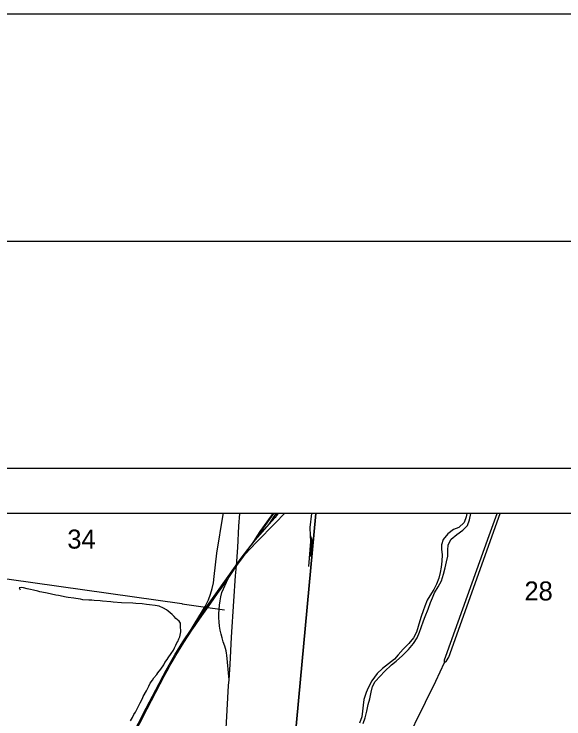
# Model space of a CAD drawing. Extents: x 0 to 34, y -3.9 to 26.2.
# Drawn here: x 3.566 to 4.778, y 20.448 to 22 of the extents above; entities that cross this region are included whole.
import ezdxf

# ---------------------------------------------------------------- set-up
doc = ezdxf.new("R2010")
doc.units = 0
for name, color, linetype in [('GM_X_City_Street', 7, 'Continuous'), ('GM_X_Interchange_Ramps', 7, 'Continuous'), ('GM_X_Interstate_Route', 7, 'Continuous'), ('GM_X_Minor_River', 7, 'Continuous'), ('GM_X_Rail_Line', 7, 'Continuous'), ('GM_X_Section_Text', 7, 'Continuous'), ('GM_X_State_Shield', 7, 'Continuous'), ('GM_X_US_Route', 7, 'Continuous'), ('SH_Border', 7, 'Continuous'), ('SH_Cut_Line', 7, 'Continuous'), ('SH_Data', 7, 'Continuous')]:
    doc.layers.add(name, color=color, linetype=linetype)

msp = doc.modelspace()

# ---------------------------------------------------------------- linework, layer by layer
at = {"layer": 'GM_X_City_Street'}
for p, q in [((3.9368, 20.7016), (3.9828, 20.6951)), ((3.9828, 20.6951), (4.0297, 20.6885))]:
    msp.add_line(p, q, dxfattribs=at)
msp.add_lwpolyline([(3.4911, 20.7646), (3.502, 20.7631), (3.9359, 20.7018), (3.9368, 20.7016)], dxfattribs=at)
at = {"layer": 'GM_X_Interchange_Ramps'}
msp.add_lwpolyline([(6.2507, 20.9), (3.4963, 20.9)], dxfattribs=at)
at = {"layer": 'GM_X_Interstate_Route'}
msp.add_lwpolyline([(8.9, 20.9), (3.1989, 20.9), (3.1952, 20.8651), (3.1898, 20.8135), (3.1846, 20.7645), (3.1788, 20.71), (3.174, 20.6648), (3.1677, 20.6059), (3.1634, 20.5651), (3.1468, 20.4087)], dxfattribs=at)
at = {"layer": 'GM_X_Minor_River'}
for points in [[(4.5639, 20.9), (4.5624, 20.893), (4.5577, 20.8806), (4.5461, 20.8697), (4.5346, 20.8654), (4.5223, 20.8558), (4.5114, 20.8427), (4.5078, 20.8313), (4.508, 20.8218), (4.5093, 20.8092), (4.509, 20.7956), (4.5072, 20.7823), (4.5051, 20.7702), (4.5019, 20.7581), (4.4974, 20.7448), (4.4911, 20.7328), (4.4821, 20.7189), (4.4767, 20.7091), (4.4711, 20.6959), (4.4675, 20.6857), (4.4635, 20.6736), (4.4606, 20.6638), (4.457, 20.6513), (4.4533, 20.6392), (4.4463, 20.6264), (4.4358, 20.6141), (4.4234, 20.6018), (4.4126, 20.5894), (4.4048, 20.5793), (4.3913, 20.5689), (4.3778, 20.5589), (4.3662, 20.5481), (4.3549, 20.532), (4.3467, 20.5162), (4.3423, 20.5063), (4.3367, 20.4909), (4.3353, 20.478), (4.3343, 20.4647), (4.3322, 20.4522), (4.327, 20.4386)], [(4.3357, 20.4377), (4.3401, 20.4505), (4.3438, 20.4653), (4.3467, 20.4797), (4.35, 20.4925), (4.3529, 20.5069), (4.3562, 20.519), (4.3621, 20.5307), (4.3726, 20.5419), (4.3826, 20.5527), (4.3981, 20.5669), (4.4085, 20.575), (4.4224, 20.5877), (4.4352, 20.6008), (4.4464, 20.6139), (4.4546, 20.6263), (4.4598, 20.6391), (4.463, 20.6493), (4.4682, 20.6636), (4.4722, 20.6735), (4.4786, 20.6897), (4.4838, 20.704), (4.4885, 20.7146), (4.4929, 20.7255), (4.5004, 20.7387), (4.5082, 20.7518), (4.5126, 20.7666), (4.5159, 20.7806), (4.5192, 20.7938), (4.5217, 20.806), (4.5224, 20.8193), (4.5226, 20.831), (4.5296, 20.8438), (4.542, 20.8542), (4.5554, 20.8639), (4.5651, 20.8736), (4.5695, 20.8864), (4.5727, 20.9)], [(3.8985, 20.5721), (3.9037, 20.5788), (3.9058, 20.5825), (3.9122, 20.5917), (3.9171, 20.5995), (3.9196, 20.6047), (3.9228, 20.6107), (3.9245, 20.6152), (3.9273, 20.6188), (3.9295, 20.6245), (3.9315, 20.6289), (3.9329, 20.6357), (3.9335, 20.6395), (3.9332, 20.6532), (3.9327, 20.6589), (3.9298, 20.6632), (3.9225, 20.6688), (3.9192, 20.6735), (3.9148, 20.6779), (3.9101, 20.6819), (3.906, 20.6851), (3.9023, 20.6879), (3.8956, 20.692), (3.8855, 20.6962), (3.8769, 20.6977), (3.8644, 20.6994), (3.8576, 20.7), (3.8481, 20.7012), (3.8341, 20.7021), (3.8277, 20.7028), (3.8026, 20.7038), (3.7844, 20.7053), (3.7791, 20.7056), (3.7613, 20.7074), (3.756, 20.7077), (3.7428, 20.7086), (3.7371, 20.7092), (3.7307, 20.7098), (3.7178, 20.7104), (3.7121, 20.7114), (3.7019, 20.7129), (3.6981, 20.7135), (3.6853, 20.7155), (3.6811, 20.7161), (3.6642, 20.7194), (3.6581, 20.7208), (3.6393, 20.7247), (3.6351, 20.7256), (3.6227, 20.728), (3.6182, 20.7293), (3.6091, 20.7312), (3.6024, 20.733), (3.5952, 20.7341), (3.5866, 20.7367), (3.5816, 20.7377), (3.5774, 20.7367), (3.5792, 20.7325)], [(3.8228, 20.4441), (3.8272, 20.4508), (3.8298, 20.4575), (3.8338, 20.4631), (3.8359, 20.4675), (3.842, 20.4787), (3.8437, 20.4832), (3.849, 20.4928), (3.8507, 20.497), (3.8577, 20.51), (3.8598, 20.5144), (3.8634, 20.5204), (3.8663, 20.5267), (3.8715, 20.533), (3.8744, 20.5382), (3.8804, 20.5455), (3.8832, 20.5496), (3.8896, 20.5573), (3.896, 20.5669), (3.8985, 20.5721)]]:
    msp.add_lwpolyline(points, dxfattribs=at)
at = {"layer": 'GM_X_Rail_Line'}
for p, q in [((4.1285, 20.8771), (4.144, 20.9)), ((4.1285, 20.8771), (4.1412, 20.8915)), ((4.1412, 20.8915), (4.1486, 20.9)), ((4.1469, 20.9), (4.1412, 20.8915)), ((4.098, 20.8426), (4.1285, 20.8771))]:
    msp.add_line(p, q, dxfattribs=at)
for points in [[(3.9655, 20.6593), (3.9872, 20.6954), (3.9944, 20.7104), (3.9993, 20.7226), (4.003, 20.7355), (4.0053, 20.7476), (4.0069, 20.7616), (4.0132, 20.8133), (4.0266, 20.8982), (4.0268, 20.9)], [(4.0378, 20.7569), (4.0452, 20.7681), (4.0564, 20.7851), (4.0682, 20.8002), (4.0755, 20.8106), (4.1003, 20.837), (4.1422, 20.8797), (4.162, 20.9)], [(4.0398, 20.5338), (4.0423, 20.568), (4.0455, 20.6283), (4.0507, 20.7076), (4.0543, 20.7632), (4.0564, 20.7851), (4.0592, 20.8252), (4.0617, 20.8723), (4.0635, 20.9)], [(4.1362, 20.9), (4.1079, 20.8606), (4.0887, 20.8309)], [(4.098, 20.8426), (4.1035, 20.8503), (4.1385, 20.9)], [(4.2196, 20.8515), (4.2187, 20.8698), (4.222, 20.9)], [(4.2157, 20.7834), (4.2203, 20.839), (4.2196, 20.8515)], [(4.2198, 20.8056), (4.2225, 20.8315), (4.2227, 20.8417), (4.2196, 20.8515)], [(3.9655, 20.6593), (4.0147, 20.7287), (4.0665, 20.8023), (4.0887, 20.8309)], [(4.0887, 20.8309), (4.0951, 20.8384), (4.098, 20.8426)], [(3.9603, 20.6467), (3.9744, 20.6675), (4, 20.7032), (4.0141, 20.7243), (4.0361, 20.7543), (4.0378, 20.7569)], [(4.0398, 20.5338), (4.0349, 20.588), (4.0343, 20.593), (4.0333, 20.598), (4.0321, 20.6029), (4.0306, 20.6078), (4.0272, 20.6176), (4.0245, 20.6262), (4.0222, 20.6349), (4.0203, 20.6437), (4.0189, 20.6525), (4.018, 20.6615), (4.0175, 20.6704), (4.0175, 20.6794), (4.0179, 20.6889), (4.0188, 20.6983), (4.0201, 20.7077), (4.0218, 20.717), (4.024, 20.7262), (4.0378, 20.7569)], [(3.8242, 20.407), (3.8571, 20.4717), (3.8855, 20.526), (3.8943, 20.5431), (3.9012, 20.5551), (3.9079, 20.5673), (3.9145, 20.5789), (3.9207, 20.5892), (3.9383, 20.618), (3.956, 20.6447), (3.9655, 20.6593)], [(3.8264, 20.4058), (3.8593, 20.4705), (3.8877, 20.5249), (3.8965, 20.5419), (3.9034, 20.5539), (3.9101, 20.5661), (3.9167, 20.5777), (3.9228, 20.5879), (3.9404, 20.6166), (3.958, 20.6434), (3.9603, 20.6467)], [(4.0057, 19.9984), (4.0196, 20.2035), (4.0292, 20.3575), (4.0342, 20.4404), (4.0389, 20.5215), (4.0398, 20.5338)]]:
    msp.add_lwpolyline(points, dxfattribs=at)
at = {"layer": 'GM_X_State_Shield'}
for points in [[(4.2313, 20.9), (3.1968, 20.9), (3.1493, 20.4095), (4.1738, 20.2814)], [(5.2454, 20.9), (4.2313, 20.9), (4.1738, 20.2814), (5.1778, 20.1897)]]:
    msp.add_lwpolyline(points, close=True, dxfattribs=at)
at = {"layer": 'GM_X_US_Route'}
for points in [[(4.5144, 20.5725), (4.5188, 20.5756), (4.5242, 20.5841), (4.6376, 20.9)], [(4.5144, 20.5725), (4.5145, 20.5778), (4.5177, 20.5862), (4.6135, 20.8516), (4.6307, 20.9)], [(4.3843, 20.3049), (4.3848, 20.3058), (4.4037, 20.3445), (4.4956, 20.531), (4.5144, 20.5725)]]:
    msp.add_lwpolyline(points, dxfattribs=at)
at = {"layer": 'SH_Border'}
msp.add_lwpolyline([(1.5, 21.5), (33.5, 21.5), (33.5, 0.5), (1.5, 0.5)], close=True, dxfattribs=at)
at = {"layer": 'SH_Cut_Line'}
msp.add_lwpolyline([(0, 0), (34, 0), (34, 22), (0, 22)], close=True, dxfattribs=at)
at = {"layer": 'SH_Data'}
msp.add_line((2, 21), (9, 21), dxfattribs=at)

# ---------------------------------------------------------------- texts
at = {"layer": 'GM_X_Section_Text'}
for s, p in [('34', (3.6835, 20.823)), ('28', (4.691, 20.7088))]:
    msp.add_text(s, height=0.04186, rotation=0, dxfattribs=at).set_placement(p)

doc.saveas('drawing.dxf')
